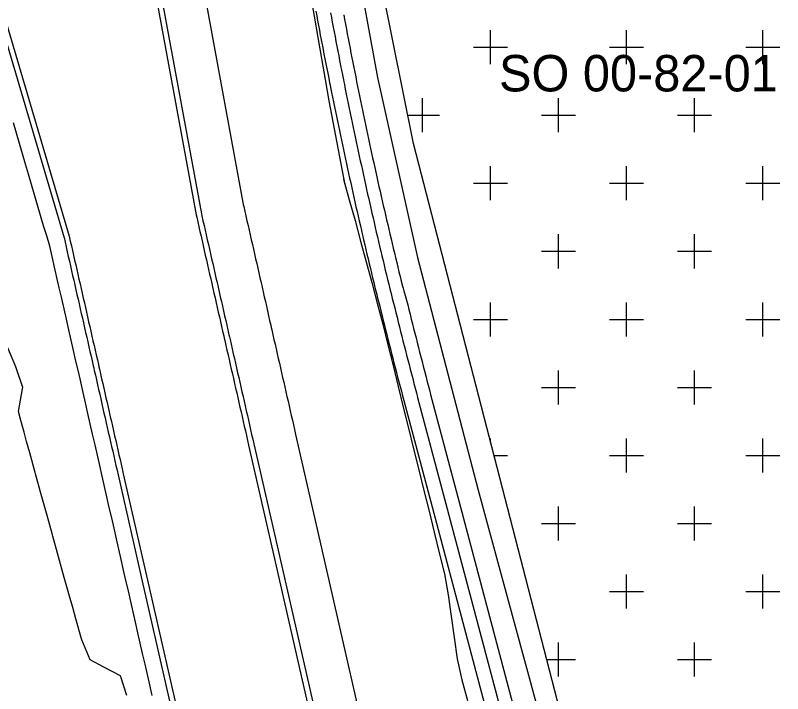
# Model space of a CAD drawing. Extents: x -723225 to -722352, y -1040354 to -1039760.
# Drawn here: x -722679.97 to -722644.15, y -1039902.99 to -1039871.34 of the extents above; entities that cross this region are included whole.
import ezdxf

# ---------------------------------------------------------------- set-up
doc = ezdxf.new("R2010")
doc.units = 0
for name, color, linetype in [('_PS_SO_číslo', 7, 'Continuous'), ('SO 00_82_01', 7, 'Continuous'), ('SO 05_30_01', 7, 'Continuous'), ('SO 05_30_03', 7, 'Continuous'), ('SO 05_73_06', 7, 'Continuous')]:
    doc.layers.add(name, color=color, linetype=linetype)

msp = doc.modelspace()

# ---------------------------------------------------------------- linework, layer by layer
at = {"layer": 'SO 00_82_01'}
for p, q in [((-722657.781, -1039873.619), (-722657.781, -1039872.031)), ((-722651.431, -1039873.619), (-722651.431, -1039872.031)), ((-722645.081, -1039873.619), (-722645.081, -1039872.031)), ((-722658.575, -1039872.825), (-722656.988, -1039872.825)), ((-722652.225, -1039872.825), (-722650.638, -1039872.825)), ((-722645.875, -1039872.825), (-722644.288, -1039872.825)), ((-722660.956, -1039876.794), (-722660.956, -1039875.206)), ((-722654.606, -1039876.794), (-722654.606, -1039875.206)), ((-722648.256, -1039876.794), (-722648.256, -1039875.206)), ((-722661.651, -1039876), (-722660.162, -1039876)), ((-722655.4, -1039876), (-722653.813, -1039876)), ((-722649.05, -1039876), (-722647.463, -1039876)), ((-722657.781, -1039879.969), (-722657.781, -1039878.381)), ((-722651.431, -1039879.969), (-722651.431, -1039878.381)), ((-722645.081, -1039879.969), (-722645.081, -1039878.381)), ((-722658.575, -1039879.175), (-722656.988, -1039879.175)), ((-722652.225, -1039879.175), (-722650.638, -1039879.175)), ((-722645.875, -1039879.175), (-722644.288, -1039879.175)), ((-722654.606, -1039883.144), (-722654.606, -1039881.556)), ((-722648.256, -1039883.144), (-722648.256, -1039881.556)), ((-722655.4, -1039882.35), (-722653.813, -1039882.35)), ((-722649.05, -1039882.35), (-722647.463, -1039882.35)), ((-722657.781, -1039886.319), (-722657.781, -1039884.731)), ((-722651.431, -1039886.319), (-722651.431, -1039884.731)), ((-722645.081, -1039886.319), (-722645.081, -1039884.731)), ((-722658.575, -1039885.525), (-722656.988, -1039885.525)), ((-722652.225, -1039885.525), (-722650.638, -1039885.525)), ((-722645.875, -1039885.525), (-722644.288, -1039885.525)), ((-722654.606, -1039889.494), (-722654.606, -1039887.906)), ((-722648.256, -1039889.494), (-722648.256, -1039887.906)), ((-722655.4, -1039888.7), (-722653.813, -1039888.7)), ((-722649.05, -1039888.7), (-722647.463, -1039888.7)), ((-722657.781, -1039891.266), (-722657.781, -1039891.081)), ((-722651.431, -1039892.669), (-722651.431, -1039891.081)), ((-722645.081, -1039892.669), (-722645.081, -1039891.081)), ((-722657.624, -1039891.875), (-722656.988, -1039891.875)), ((-722652.225, -1039891.875), (-722650.638, -1039891.875)), ((-722645.875, -1039891.875), (-722644.288, -1039891.875)), ((-722654.606, -1039895.844), (-722654.606, -1039894.256)), ((-722648.256, -1039895.844), (-722648.256, -1039894.256)), ((-722655.4, -1039895.05), (-722653.813, -1039895.05)), ((-722649.05, -1039895.05), (-722647.463, -1039895.05)), ((-722651.431, -1039899.019), (-722651.431, -1039897.431)), ((-722645.081, -1039899.019), (-722645.081, -1039897.431)), ((-722652.225, -1039898.225), (-722650.638, -1039898.225)), ((-722645.875, -1039898.225), (-722644.288, -1039898.225)), ((-722654.606, -1039902.194), (-722654.606, -1039900.606)), ((-722648.256, -1039902.194), (-722648.256, -1039900.606)), ((-722655.161, -1039901.4), (-722653.813, -1039901.4)), ((-722649.05, -1039901.4), (-722647.463, -1039901.4))]:
    msp.add_line(p, q, dxfattribs=at)
msp.add_lwpolyline([(-722650.216, -1039834.921), (-722645.223, -1039840.782), (-722642.449, -1039848.104), (-722634.117, -1039888.119), (-722624.049, -1039921.624), (-722623.844, -1039922.152), (-722642.695, -1039936.685), (-722643.343, -1039936.996), (-722644.356, -1039937.197), (-722644.6, -1039936.791), (-722653.569, -1039907.557), (-722661.386, -1039877.326), (-722662.841, -1039870.039), (-722665.351, -1039856.317), (-722666.514, -1039851.426), (-722668.589, -1039846.589), (-722670.486, -1039843.494), (-722673.151, -1039840.205), (-722675.847, -1039837.714)], dxfattribs=at)
at = {"layer": 'SO 05_30_01'}
msp.add_lwpolyline([(-722674.76, -1039903.067), (-722675.056, -1039902.159), (-722675.836, -1039901.75), (-722676.47, -1039901.417), (-722676.863, -1039900.475), (-722676.877, -1039900.425), (-722677.136, -1039899.504), (-722677.285, -1039898.973), (-722677.407, -1039898.541), (-722677.558, -1039898.008), (-722677.68, -1039897.567), (-722677.95, -1039896.601), (-722678.22, -1039895.635), (-722678.234, -1039895.585), (-722678.488, -1039894.669), (-722678.636, -1039894.134), (-722678.758, -1039893.692), (-722679.026, -1039892.725), (-722679.04, -1039892.674), (-722679.292, -1039891.758), (-722679.439, -1039891.223), (-722679.558, -1039890.786), (-722679.705, -1039890.251), (-722679.822, -1039889.819), (-722679.638, -1039888.762), (-722679.622, -1039888.704), (-722679.921, -1039887.791), (-722679.942, -1039887.74), (-722680.313, -1039886.847)], dxfattribs=at)
at = {"layer": 'SO 05_30_03'}
for p, q in [((-722673.693, -1039856.521), (-722669.314, -1039880.238)), ((-722675.887, -1039857.021), (-722671.527, -1039880.646)), ((-722675.641, -1039856.976), (-722671.281, -1039880.601)), ((-722684.414, -1039858.981), (-722677.693, -1039881.718)), ((-722684.174, -1039858.91), (-722677.453, -1039881.647))]:
    msp.add_line(p, q, dxfattribs=at)
for points in [[(-722664.569, -1039879.255), (-722664.758, -1039878.273), (-722664.946, -1039877.291), (-722665.134, -1039876.309), (-722665.316, -1039875.325), (-722665.486, -1039874.34), (-722665.656, -1039873.354), (-722665.826, -1039872.369), (-722665.997, -1039871.383), (-722666.167, -1039870.398)], [(-722665.94, -1039871.14), (-722665.899, -1039871.363), (-722665.857, -1039871.587), (-722665.815, -1039871.811), (-722665.773, -1039872.034), (-722665.731, -1039872.258), (-722665.688, -1039872.481), (-722665.645, -1039872.704), (-722665.602, -1039872.928), (-722665.559, -1039873.151), (-722665.516, -1039873.374), (-722665.472, -1039873.597), (-722665.428, -1039873.82), (-722665.384, -1039874.043), (-722665.34, -1039874.266), (-722665.296, -1039874.489), (-722665.274, -1039874.596), (-722665.251, -1039874.712), (-722665.206, -1039874.935), (-722665.161, -1039875.158), (-722665.116, -1039875.381), (-722665.07, -1039875.604), (-722665.024, -1039875.826), (-722664.978, -1039876.049), (-722664.932, -1039876.271), (-722664.886, -1039876.494), (-722664.839, -1039876.716), (-722664.792, -1039876.939), (-722664.745, -1039877.161), (-722664.698, -1039877.384), (-722664.651, -1039877.606), (-722664.603, -1039877.828), (-722664.555, -1039878.05), (-722664.507, -1039878.272), (-722664.459, -1039878.495), (-722664.41, -1039878.717), (-722664.361, -1039878.939), (-722664.313, -1039879.161), (-722664.263, -1039879.382), (-722664.214, -1039879.604), (-722664.164, -1039879.826), (-722664.115, -1039880.048), (-722664.065, -1039880.27), (-722664.014, -1039880.491), (-722663.964, -1039880.713), (-722663.913, -1039880.934), (-722663.862, -1039881.156), (-722663.811, -1039881.377), (-722663.76, -1039881.599), (-722663.708, -1039881.82), (-722663.657, -1039882.041), (-722663.605, -1039882.263), (-722663.553, -1039882.484), (-722663.5, -1039882.705), (-722663.448, -1039882.926), (-722663.395, -1039883.147), (-722663.342, -1039883.368), (-722663.289, -1039883.589), (-722663.235, -1039883.81), (-722663.182, -1039884.031), (-722663.127, -1039884.252), (-722663.1, -1039884.357), (-722663.07, -1039884.472), (-722663.013, -1039884.692), (-722662.957, -1039884.912), (-722662.903, -1039885.133), (-722662.848, -1039885.354), (-722662.793, -1039885.574), (-722662.738, -1039885.795), (-722662.683, -1039886.015), (-722662.628, -1039886.236), (-722662.572, -1039886.456), (-722662.516, -1039886.677), (-722662.46, -1039886.897), (-722662.404, -1039887.117), (-722662.347, -1039887.337), (-722662.291, -1039887.558), (-722662.234, -1039887.778), (-722662.177, -1039887.998), (-722662.12, -1039888.218), (-722662.062, -1039888.438), (-722662.004, -1039888.658), (-722661.946, -1039888.878), (-722661.888, -1039889.098), (-722661.83, -1039889.317), (-722660.575, -1039894.038), (-722658.004, -1039903.708)], [(-722665.255, -1039871.217), (-722665.213, -1039871.44), (-722665.172, -1039871.664), (-722665.129, -1039871.887), (-722665.087, -1039872.111), (-722665.045, -1039872.334), (-722665.002, -1039872.558), (-722664.959, -1039872.781), (-722664.916, -1039873.004), (-722664.872, -1039873.227), (-722664.829, -1039873.451), (-722664.785, -1039873.674), (-722664.741, -1039873.897), (-722664.697, -1039874.12), (-722664.652, -1039874.343), (-722664.631, -1039874.449), (-722664.607, -1039874.566), (-722664.563, -1039874.789), (-722664.517, -1039875.011), (-722664.472, -1039875.234), (-722664.427, -1039875.457), (-722664.381, -1039875.68), (-722664.335, -1039875.902), (-722664.289, -1039876.125), (-722664.242, -1039876.347), (-722664.196, -1039876.57), (-722664.149, -1039876.792), (-722664.102, -1039877.015), (-722664.055, -1039877.237), (-722664.007, -1039877.459), (-722663.96, -1039877.681), (-722663.912, -1039877.904), (-722663.864, -1039878.126), (-722663.815, -1039878.348), (-722663.767, -1039878.57), (-722663.718, -1039878.792), (-722663.669, -1039879.014), (-722663.62, -1039879.236), (-722663.57, -1039879.458), (-722663.521, -1039879.679), (-722663.471, -1039879.901), (-722663.421, -1039880.123), (-722663.371, -1039880.344), (-722663.32, -1039880.566), (-722663.27, -1039880.788), (-722663.219, -1039881.009), (-722663.168, -1039881.231), (-722663.116, -1039881.452), (-722663.065, -1039881.673), (-722663.013, -1039881.895), (-722662.961, -1039882.116), (-722662.909, -1039882.337), (-722662.857, -1039882.558), (-722662.804, -1039882.779), (-722662.751, -1039883), (-722662.698, -1039883.222), (-722662.645, -1039883.442), (-722662.592, -1039883.663), (-722662.538, -1039883.884), (-722662.484, -1039884.105), (-722662.456, -1039884.21), (-722662.427, -1039884.325), (-722662.37, -1039884.545), (-722662.313, -1039884.765), (-722662.259, -1039884.986), (-722662.204, -1039885.207), (-722662.15, -1039885.427), (-722662.095, -1039885.648), (-722662.04, -1039885.869), (-722661.984, -1039886.089), (-722661.929, -1039886.309), (-722661.873, -1039886.53), (-722661.817, -1039886.75), (-722661.76, -1039886.97), (-722661.704, -1039887.191), (-722661.647, -1039887.411), (-722661.59, -1039887.631), (-722661.533, -1039887.851), (-722661.476, -1039888.071), (-722661.419, -1039888.291), (-722661.361, -1039888.511), (-722661.303, -1039888.731), (-722661.245, -1039888.951), (-722661.187, -1039889.171), (-722659.932, -1039893.891), (-722657.361, -1039903.562)], [(-722664.64, -1039871.31), (-722664.598, -1039871.533), (-722664.556, -1039871.757), (-722664.514, -1039871.98), (-722664.471, -1039872.204), (-722664.428, -1039872.427), (-722664.386, -1039872.65), (-722664.342, -1039872.874), (-722664.299, -1039873.097), (-722664.255, -1039873.32), (-722664.212, -1039873.543), (-722664.167, -1039873.766), (-722664.123, -1039873.989), (-722664.079, -1039874.212), (-722664.057, -1039874.319), (-722664.034, -1039874.435), (-722663.989, -1039874.658), (-722663.944, -1039874.881), (-722663.899, -1039875.103), (-722663.853, -1039875.326), (-722663.808, -1039875.549), (-722663.762, -1039875.771), (-722663.715, -1039875.994), (-722663.669, -1039876.217), (-722663.622, -1039876.439), (-722663.576, -1039876.661), (-722663.528, -1039876.884), (-722663.481, -1039877.106), (-722663.433, -1039877.328), (-722663.385, -1039877.55), (-722663.336, -1039877.772), (-722663.288, -1039877.995), (-722663.239, -1039878.217), (-722663.19, -1039878.438), (-722663.141, -1039878.66), (-722663.092, -1039878.882), (-722663.042, -1039879.104), (-722662.992, -1039879.326), (-722662.942, -1039879.548), (-722662.892, -1039879.769), (-722662.842, -1039879.991), (-722662.791, -1039880.212), (-722662.74, -1039880.434), (-722662.689, -1039880.655), (-722662.638, -1039880.877), (-722662.586, -1039881.098), (-722662.534, -1039881.319), (-722662.483, -1039881.541), (-722662.43, -1039881.762), (-722662.378, -1039881.983), (-722662.325, -1039882.204), (-722662.272, -1039882.425), (-722662.219, -1039882.646), (-722662.166, -1039882.867), (-722662.113, -1039883.088), (-722662.059, -1039883.309), (-722662.005, -1039883.53), (-722661.951, -1039883.75), (-722661.896, -1039883.971), (-722661.867, -1039884.076), (-722661.836, -1039884.19), (-722661.771, -1039884.409), (-722661.707, -1039884.627), (-722661.648, -1039884.847), (-722661.593, -1039885.067), (-722661.538, -1039885.288), (-722661.484, -1039885.509), (-722661.429, -1039885.729), (-722661.374, -1039885.95), (-722661.318, -1039886.17), (-722661.263, -1039886.391), (-722661.207, -1039886.611), (-722661.151, -1039886.832), (-722661.095, -1039887.052), (-722661.038, -1039887.272), (-722660.982, -1039887.492), (-722660.925, -1039887.712), (-722660.868, -1039887.933), (-722660.811, -1039888.153), (-722660.753, -1039888.373), (-722660.696, -1039888.593), (-722660.638, -1039888.812), (-722660.58, -1039889.032), (-722659.33, -1039893.754), (-722656.76, -1039903.425)], [(-722680.074, -1039876.344), (-722679.932, -1039876.823), (-722679.791, -1039877.303), (-722679.65, -1039877.783), (-722679.508, -1039878.262), (-722679.367, -1039878.742), (-722679.226, -1039879.221), (-722679.084, -1039879.701), (-722678.943, -1039880.181), (-722678.802, -1039880.66), (-722678.66, -1039881.14), (-722678.519, -1039881.619), (-722678.378, -1039882.099), (-722678.361, -1039882.155)], [(-722664.643, -1039878.979), (-722664.377, -1039879.944), (-722664.111, -1039880.909), (-722663.85, -1039881.875), (-722663.592, -1039882.842), (-722663.333, -1039883.809), (-722663.075, -1039884.776), (-722662.817, -1039885.743), (-722662.576, -1039886.713), (-722662.336, -1039887.684), (-722662.096, -1039888.655), (-722661.856, -1039889.626), (-722661.616, -1039890.597), (-722661.376, -1039891.568), (-722661.136, -1039892.539), (-722660.896, -1039893.51), (-722660.656, -1039894.481), (-722660.416, -1039895.452), (-722660.176, -1039896.423), (-722659.936, -1039897.394), (-722659.757, -1039898.379), (-722659.617, -1039899.372), (-722659.476, -1039900.366), (-722659.335, -1039901.36), (-722659.132, -1039902.339), (-722658.86, -1039903.302)], [(-722669.327, -1039880.168), (-722669.307, -1039880.257), (-722669.257, -1039880.478), (-722669.206, -1039880.7), (-722669.156, -1039880.921), (-722669.105, -1039881.143), (-722669.055, -1039881.365), (-722669.004, -1039881.586), (-722668.954, -1039881.808), (-722668.903, -1039882.029), (-722668.853, -1039882.251), (-722668.802, -1039882.473), (-722668.751, -1039882.694), (-722668.701, -1039882.916), (-722668.65, -1039883.137), (-722668.6, -1039883.359), (-722668.549, -1039883.58), (-722668.499, -1039883.802), (-722668.448, -1039884.024), (-722668.398, -1039884.245), (-722668.347, -1039884.467), (-722668.297, -1039884.688), (-722668.246, -1039884.91), (-722668.196, -1039885.132), (-722668.145, -1039885.353), (-722668.095, -1039885.575), (-722668.044, -1039885.796), (-722668.02, -1039885.902), (-722667.994, -1039886.018), (-722667.943, -1039886.24), (-722667.893, -1039886.461), (-722667.842, -1039886.683), (-722667.792, -1039886.904), (-722667.741, -1039887.126), (-722667.691, -1039887.347), (-722667.64, -1039887.569), (-722667.59, -1039887.791), (-722667.539, -1039888.012), (-722667.489, -1039888.234), (-722667.438, -1039888.455), (-722667.388, -1039888.677), (-722667.337, -1039888.899), (-722667.287, -1039889.12), (-722667.236, -1039889.342), (-722667.186, -1039889.563), (-722667.135, -1039889.785), (-722667.085, -1039890.007), (-722667.034, -1039890.228), (-722666.984, -1039890.45), (-722666.933, -1039890.671), (-722666.883, -1039890.893), (-722665.798, -1039895.652), (-722663.575, -1039905.402)], [(-722671.527, -1039880.646), (-722671.502, -1039880.757), (-722671.451, -1039880.979), (-722671.401, -1039881.2), (-722671.35, -1039881.422), (-722671.3, -1039881.643), (-722671.249, -1039881.865), (-722671.199, -1039882.086), (-722671.148, -1039882.308), (-722671.098, -1039882.53), (-722671.047, -1039882.751), (-722670.997, -1039882.973), (-722670.946, -1039883.194), (-722670.896, -1039883.416), (-722670.845, -1039883.638), (-722670.795, -1039883.859), (-722670.744, -1039884.081), (-722670.694, -1039884.302), (-722670.643, -1039884.524), (-722670.593, -1039884.746), (-722670.542, -1039884.967), (-722670.492, -1039885.189), (-722670.441, -1039885.41), (-722670.391, -1039885.632), (-722670.34, -1039885.853), (-722670.29, -1039886.075), (-722670.239, -1039886.297), (-722670.215, -1039886.403), (-722670.189, -1039886.518), (-722670.138, -1039886.74), (-722670.087, -1039886.961), (-722670.037, -1039887.183), (-722669.986, -1039887.405), (-722669.936, -1039887.626), (-722669.885, -1039887.848), (-722669.835, -1039888.069), (-722669.784, -1039888.291), (-722669.734, -1039888.513), (-722669.683, -1039888.734), (-722669.633, -1039888.956), (-722669.582, -1039889.177), (-722669.532, -1039889.399), (-722669.481, -1039889.62), (-722669.431, -1039889.842), (-722669.38, -1039890.064), (-722669.33, -1039890.285), (-722669.279, -1039890.507), (-722669.229, -1039890.728), (-722669.178, -1039890.95), (-722669.128, -1039891.172), (-722669.077, -1039891.393), (-722667.992, -1039896.153), (-722665.77, -1039905.902)], [(-722671.282, -1039880.596), (-722671.258, -1039880.701), (-722671.208, -1039880.923), (-722671.157, -1039881.145), (-722671.107, -1039881.366), (-722671.056, -1039881.588), (-722671.006, -1039881.809), (-722670.955, -1039882.031), (-722670.904, -1039882.253), (-722670.854, -1039882.474), (-722670.803, -1039882.696), (-722670.753, -1039882.917), (-722670.702, -1039883.139), (-722670.652, -1039883.36), (-722670.601, -1039883.582), (-722670.551, -1039883.804), (-722670.5, -1039884.025), (-722670.45, -1039884.247), (-722670.399, -1039884.468), (-722670.349, -1039884.69), (-722670.298, -1039884.912), (-722670.248, -1039885.133), (-722670.197, -1039885.355), (-722670.147, -1039885.576), (-722670.096, -1039885.798), (-722670.046, -1039886.02), (-722669.995, -1039886.241), (-722669.971, -1039886.347), (-722669.945, -1039886.463), (-722669.894, -1039886.684), (-722669.844, -1039886.906), (-722669.793, -1039887.127), (-722669.743, -1039887.349), (-722669.692, -1039887.571), (-722669.642, -1039887.792), (-722669.591, -1039888.014), (-722669.541, -1039888.235), (-722669.49, -1039888.457), (-722669.44, -1039888.679), (-722669.389, -1039888.9), (-722669.339, -1039889.122), (-722669.288, -1039889.343), (-722669.238, -1039889.565), (-722669.187, -1039889.787), (-722669.137, -1039890.008), (-722669.086, -1039890.23), (-722669.036, -1039890.451), (-722668.985, -1039890.673), (-722668.935, -1039890.894), (-722668.884, -1039891.116), (-722668.833, -1039891.338), (-722667.749, -1039896.097), (-722665.526, -1039905.847)], [(-722677.695, -1039881.711), (-722677.646, -1039881.924), (-722677.595, -1039882.146), (-722677.545, -1039882.368), (-722677.494, -1039882.589), (-722677.444, -1039882.811), (-722677.393, -1039883.032), (-722677.343, -1039883.254), (-722677.292, -1039883.476), (-722677.242, -1039883.697), (-722677.191, -1039883.919), (-722677.141, -1039884.14), (-722677.09, -1039884.362), (-722677.04, -1039884.583), (-722676.989, -1039884.805), (-722676.939, -1039885.027), (-722676.888, -1039885.248), (-722676.838, -1039885.47), (-722676.787, -1039885.691), (-722676.737, -1039885.913), (-722676.686, -1039886.135), (-722676.636, -1039886.356), (-722676.585, -1039886.578), (-722676.535, -1039886.799), (-722676.484, -1039887.021), (-722676.434, -1039887.243), (-722676.383, -1039887.464), (-722676.333, -1039887.686), (-722676.309, -1039887.792), (-722676.282, -1039887.907), (-722676.232, -1039888.129), (-722676.181, -1039888.351), (-722676.131, -1039888.572), (-722676.08, -1039888.794), (-722676.03, -1039889.015), (-722675.979, -1039889.237), (-722675.929, -1039889.458), (-722675.878, -1039889.68), (-722675.828, -1039889.902), (-722675.777, -1039890.123), (-722675.727, -1039890.345), (-722675.676, -1039890.566), (-722675.626, -1039890.788), (-722675.575, -1039891.01), (-722675.525, -1039891.231), (-722675.474, -1039891.453), (-722675.423, -1039891.674), (-722675.373, -1039891.896), (-722675.322, -1039892.118), (-722675.272, -1039892.339), (-722675.221, -1039892.561), (-722675.171, -1039892.782), (-722674.086, -1039897.542), (-722671.863, -1039907.292)], [(-722677.453, -1039881.647), (-722677.402, -1039881.869), (-722677.352, -1039882.09), (-722677.301, -1039882.312), (-722677.251, -1039882.534), (-722677.2, -1039882.755), (-722677.15, -1039882.977), (-722677.099, -1039883.198), (-722677.049, -1039883.42), (-722676.998, -1039883.642), (-722676.948, -1039883.863), (-722676.897, -1039884.085), (-722676.847, -1039884.306), (-722676.796, -1039884.528), (-722676.746, -1039884.75), (-722676.695, -1039884.971), (-722676.645, -1039885.193), (-722676.594, -1039885.414), (-722676.544, -1039885.636), (-722676.493, -1039885.857), (-722676.443, -1039886.079), (-722676.392, -1039886.301), (-722676.342, -1039886.522), (-722676.291, -1039886.744), (-722676.24, -1039886.965), (-722676.19, -1039887.187), (-722676.139, -1039887.409), (-722676.089, -1039887.63), (-722676.065, -1039887.736), (-722676.038, -1039887.852), (-722675.988, -1039888.073), (-722675.937, -1039888.295), (-722675.887, -1039888.517), (-722675.836, -1039888.738), (-722675.786, -1039888.96), (-722675.735, -1039889.181), (-722675.685, -1039889.403), (-722675.634, -1039889.624), (-722675.584, -1039889.846), (-722675.533, -1039890.068), (-722675.483, -1039890.289), (-722675.432, -1039890.511), (-722675.382, -1039890.732), (-722675.331, -1039890.954), (-722675.281, -1039891.176), (-722675.23, -1039891.397), (-722675.18, -1039891.619), (-722675.129, -1039891.84), (-722675.079, -1039892.062), (-722675.028, -1039892.284), (-722674.978, -1039892.505), (-722674.927, -1039892.727), (-722673.842, -1039897.486), (-722671.62, -1039907.236)], [(-722678.373, -1039882.109), (-722678.262, -1039882.597), (-722678.151, -1039883.084), (-722678.04, -1039883.572), (-722677.929, -1039884.059), (-722677.817, -1039884.547), (-722677.706, -1039885.034), (-722677.595, -1039885.522), (-722677.484, -1039886.009), (-722677.373, -1039886.497), (-722677.262, -1039886.984), (-722677.151, -1039887.472), (-722677.04, -1039887.959), (-722676.928, -1039888.447), (-722676.817, -1039888.934), (-722676.706, -1039889.422), (-722676.595, -1039889.909), (-722676.484, -1039890.397), (-722676.373, -1039890.884), (-722676.262, -1039891.372), (-722676.151, -1039891.859), (-722676.039, -1039892.347), (-722675.928, -1039892.834), (-722675.817, -1039893.322), (-722675.706, -1039893.809), (-722675.595, -1039894.297), (-722675.484, -1039894.784), (-722675.373, -1039895.272), (-722675.262, -1039895.759), (-722675.15, -1039896.247), (-722675.039, -1039896.734), (-722674.928, -1039897.222), (-722674.817, -1039897.709), (-722674.706, -1039898.197), (-722674.595, -1039898.684), (-722674.484, -1039899.172), (-722674.373, -1039899.659), (-722674.261, -1039900.147), (-722674.15, -1039900.634), (-722674.039, -1039901.122), (-722673.928, -1039901.609), (-722673.817, -1039902.097), (-722673.706, -1039902.584), (-722673.595, -1039903.071)]]:
    msp.add_lwpolyline(points, dxfattribs=at)
at = {"layer": 'SO 05_73_06'}
msp.add_lwpolyline([(-722675.338, -1039839.487), (-722674.61, -1039840.175), (-722673.54, -1039841.25), (-722671.932, -1039843.21), (-722670.5, -1039845.293), (-722670.238, -1039845.721), (-722669.981, -1039846.155), (-722669.783, -1039846.502), (-722669.488, -1039847.039), (-722669.11, -1039847.768), (-722668.806, -1039848.395), (-722668.389, -1039849.32), (-722668.007, -1039850.252), (-722667.653, -1039851.205), (-722667.187, -1039852.651), (-722666.701, -1039854.524), (-722664.886, -1039864.296), (-722663.054, -1039874.238), (-722661.194, -1039882.633), (-722658.363, -1039893.498), (-722652.26, -1039915.899), (-722650.207, -1039922.272), (-722636.534, -1039939.241)], dxfattribs=at)

# ---------------------------------------------------------------- texts
at = {"layer": '_PS_SO_číslo'}
msp.add_text('SO 00-82-01', height=1.7, dxfattribs=at).set_placement((-722657.39, -1039874.89))

doc.saveas('drawing.dxf')
